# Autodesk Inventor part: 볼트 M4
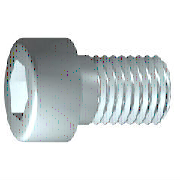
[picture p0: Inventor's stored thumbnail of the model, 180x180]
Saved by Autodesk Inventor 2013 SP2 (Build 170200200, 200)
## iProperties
IsCustomPart: 0
Created: 2009-02
Part Number: 볼트 M4
Material: 강철, 연강
Description: 6각머리 태핑 나사
Document SubType Name: Modeling
Standard: KS B 1003
Standards Organization: KS
Language: ko-KR
Size Designation: M 4 x 12
Categories: <MemberInstance><Categories><Category DisplayName="조임쇠" InternalName="e4da775c-781d-43d5-af7c-5136215cf5a6" Mnemonic="FSTN"><Category DisplayName="볼트" InternalN
Density: 1 g/cm^3
Author: pww
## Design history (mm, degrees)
sketch "스케치1"
  geometry: L1 (-1, 0)-(12, 0); L2 (12, 0)-(12, 2); L3 (12, 2)-(1.75, 2); L4 (1.75, 2)-(1.32, 2); L5 (1.32, 2)-(0, 2); L6 (0, 2)-(0, 3.5); L7 (0, 3.5)-(-4, 3.5); L8 (-4, 3.5)-(-4, 1.732); L9 (-4, 1.732)-(-2, 1.732); L10 (-2, 1.732)-(-1, 0); L11 (-7.2, 0)-(15.2, 0) reference; L12 (0, -0.7)-(0, 4.2) reference; L13 (1.75, 2)-(0, 2)
  constraints: 22 end point, 6 parallel, 2 collinear, 2 perpendicular, 1 horizontal, 1 point on line
  dimensions: "d1" = 10.25 distance from line of L3.end L2 (= GEL); "d2" = 0.42952 distance of L4.end L3.end (computed from GAL); "d3" = 4 distance between parallel lines of L8 L6 (= KOH); "d4" = 2 distance of L8.end L9.end (= INTI); "d5" = 60 deg angle of L10 L1; "d6" = 4 diameter of L3 L1 (= GD); "d7" = 4 diameter of L5 L1 (= BDM); "d8" = 3.4641 diameter of L9 L1 (= 1.1547 x SW); "d9" = 7 diameter of L7 L1 (= KOD); "d26" = 12 distance between parallel lines of L12 L2 (= NLG)
revolve "본체" sketch "스케치1" stored, may be unused: angle "d10" = 90 deg
sketch "스케치2"
  geometry: L1 (0, -4.9)-(0, 4.9) reference; L2 (-4.9, 0)-(4.9, 0) reference; L3 (1.732, 0)-(0.866, -1.5); L4 (0.866, -1.5)-(-0.866, -1.5); L5 (-0.866, -1.5)-(-1.732, 0); L6 (-1.732, 0)-(-0.866, 1.5); L7 (-0.866, 1.5)-(0.866, 1.5); L8 (0.866, 1.5)-(1.732, 0); 2 further points
  constraints: 12 end point, 1 coincident, 1 horizontal alignment, 1 point on line, 12 other
extrude "슬롯" join sketch "스케치2" stored distance "d11" = 10; taper "d12" = 0 deg
workplane "Work Plane1"
fillet "Fillet2" dims "d30" = 0.1 (= R)
body "Solid1"
fillet "모깎기1" dims "d17" = 0.4 (= RR)
feature "스레드" dims "d13" = 10.25 (= GEL), "d14" = 0
chamfer "모따기1" distance "d15" = 0.42941 (= -0.5 x SPD + 0.5 x GD); stored, may be unused: second distance "d16" = 0.42941 (= GUL), angle "d27" = 45 deg
other parameters: "GD" = 4 (= NND) [user parameter; used in 2 equation terms], "NLG" = 12 [user parameter; used in 1 equation term], "GEL" = 10.25 [user parameter; used in 2 equation terms], "KOD" = 7 [user parameter; used in 1 equation term], "KOH" = 4 [user parameter; used in 1 equation term], "INTI" = 2 [user parameter; used in 1 equation term], "GAL" = 0.42941 (= 0.61345 x PTC) [user parameter; used in 1 equation term], "GUL" = 0.42941 (= 0.61345 x PTC) [user parameter; used in 1 equation term], "BDM" = 4 (= NND) [user parameter; used in 1 equation term], "SW" = 3 [user parameter; used in 2 equation terms], "RR" = 0.4 [user parameter; used in 1 equation term], "SPD" = 3.14117 (= NND - 1.2269 x PTC) [user parameter; used in 1 equation term], "d19" = 0, "d28" = 0, "d29" = 0, "R" = 0.1 [user parameter; used in 1 equation term], "PHH" = 0.2 [user parameter], "GD1" = 3.14117 (= THREADDIA - 1.2269 x PTC) [user parameter], "THREADDIA" = 4 [user parameter; used in 1 equation term], "FAWI" = 45 deg [user parameter], "TPU" = 14.28571 (computed from PTC) [user parameter], "PTC" = 0.7 [user parameter; used in 5 equation terms], "NND" = 4 [user parameter; used in 3 equation terms], "TOA" = 30 deg [user parameter], "E0" = 3.465 (= 1.155 x SW) [user parameter]
